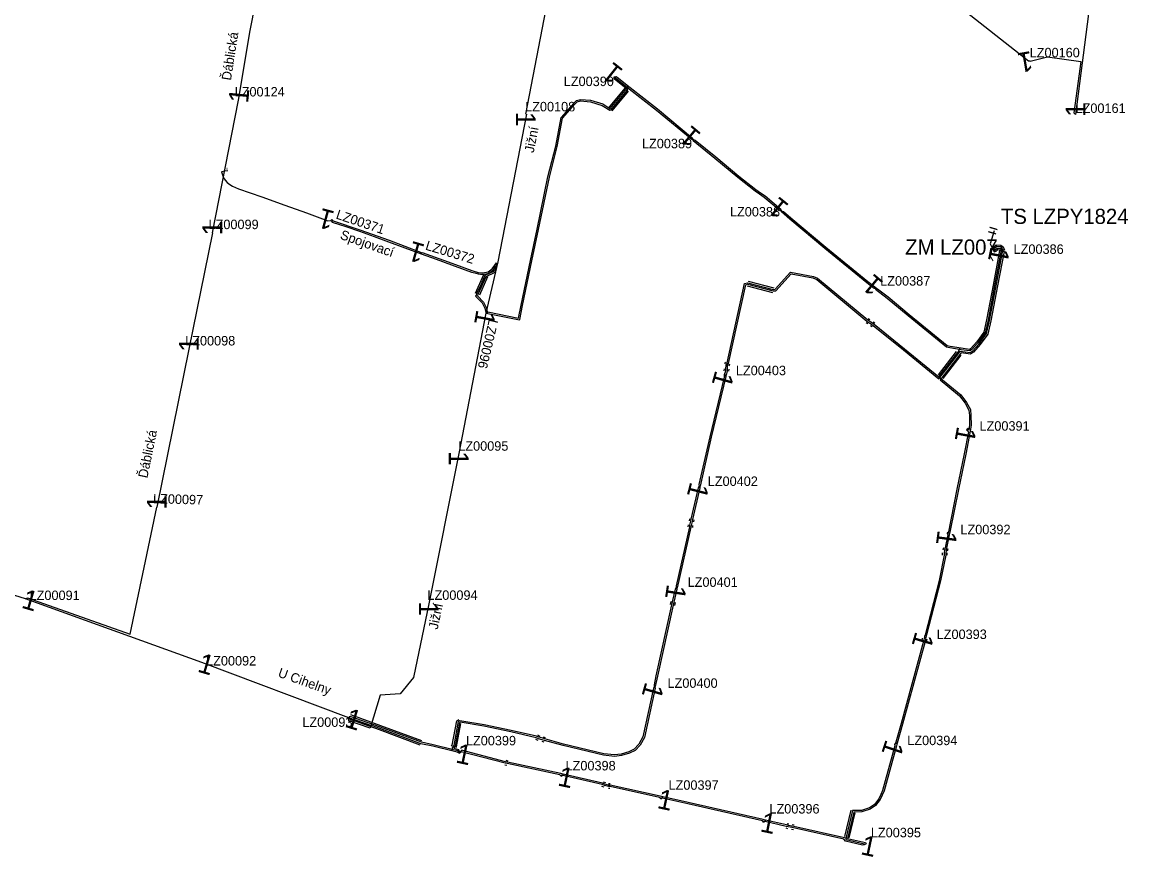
# Model space of a CAD drawing. Extents: x -736540 to -735418, y -1033000 to -1031598.
# Drawn here: x -735947.1 to -735655.8, y -1032999.9 to -1032780 of the extents above; entities that cross this region are included whole.
import ezdxf

# ---------------------------------------------------------------- set-up
doc = ezdxf.new("R2010")
doc.units = 0
for name, color, linetype in [('ftf_2010', 7, 'Continuous'), ('ftf_2060', 7, 'Continuous'), ('ftf_2100', 7, 'Continuous'), ('ftf_2140', 7, 'Continuous'), ('ftf_2210', 7, 'Continuous'), ('ftf_3010', 7, 'Continuous'), ('ftf_3010_ftf_3010_gtda_3015_gtda_3015_1', 7, 'Continuous'), ('ftf_3150', 7, 'Continuous'), ('ftf_3150_ftf_3150_gtda_3155_gtda_3155_1', 7, 'Continuous'), ('ftf_3160', 7, 'Continuous'), ('ftf_3160_ftf_3160_gtda_3165_gtda_3165_1', 7, 'Continuous'), ('ftf_3210', 7, 'Continuous'), ('ftf_nu', 7, 'Continuous')]:
    doc.layers.add(name, color=color, linetype=linetype)

msp = doc.modelspace()

# ---------------------------------------------------------------- linework, layer by layer
at = {"layer": 'ftf_2010'}
for points in [[(-735890.13, -1032800.57), (-735887.02, -1032782.2), (-735881.14, -1032752.3)], [(-735814.42, -1032804.25), (-735807.64, -1032769.14)], [(-735681.54, -1032790.25), (-735682.02, -1032790.23), (-735700.9, -1032775.41)], [(-735665.87, -1032775.1), (-735669.61, -1032804.33)], [(-735681.54, -1032790.25), (-735677.04, -1032789.09), (-735668.26, -1032790.39), (-735670.05, -1032803.87), (-735669.61, -1032804.33)], [(-735770.15, -1032811.01), (-735770.65, -1032810.99), (-735779.98, -1032803.26), (-735787.2, -1032797.62), (-735790.76, -1032794.7), (-735790.78, -1032794.47), (-735790.63, -1032794.3)], [(-735746.97, -1032829.81), (-735747.4, -1032829.7), (-735751.62, -1032826.16), (-735752.83, -1032825.33), (-735754.05, -1032824.5), (-735758.59, -1032820.92), (-735764.61, -1032815.88), (-735770.34, -1032811.25), (-735770.15, -1032811.01)], [(-735722.08, -1032850.15), (-735722.62, -1032850.2), (-735724.58, -1032848.7), (-735735.63, -1032839.65), (-735744.85, -1032831.9), (-735747.1, -1032829.96), (-735746.97, -1032829.81)], [(-735865.81, -1032832.27), (-735865.62, -1032832.46), (-735865.43, -1032832.64), (-735861.85, -1032833.84), (-735858.28, -1032835.04), (-735854.42, -1032836.45), (-735850.56, -1032837.85), (-735846.3, -1032839.42), (-735842.04, -1032840.99)], [(-735897.01, -1032835.52), (-735903.17, -1032866.17)], [(-735762.13, -1032872.86), (-735761.6, -1032872.99), (-735761.34, -1032871.9), (-735761.3, -1032871.42), (-735761.26, -1032870.37), (-735761.04, -1032869.89), (-735756.48, -1032849.16), (-735756.03, -1032849.04), (-735749.31, -1032850.8), (-735748.55, -1032850.74), (-735744.57, -1032846.33), (-735738.79, -1032847.35), (-735737.76, -1032847.81), (-735724.61, -1032858.75), (-735723.76, -1032859.29), (-735723.37, -1032859.57), (-735722.94, -1032859.87), (-735714.9, -1032866.34), (-735705.59, -1032873.97), (-735700.33, -1032867.22), (-735700, -1032866.68), (-735697.38, -1032867.04), (-735696.77, -1032866.66), (-735695.9, -1032865.68), (-735695.02, -1032864.7), (-735693.06, -1032861.98), (-735692.28, -1032858.62), (-735690.53, -1032849.43), (-735688.78, -1032840.08), (-735688.99, -1032839.39), (-735689.37, -1032839.14), (-735690.35, -1032839.1), (-735690.97, -1032839.59), (-735691.03, -1032840.5)], [(-735691.03, -1032840.5), (-735690.72, -1032839.9), (-735690.22, -1032839.5), (-735689.5, -1032839.53), (-735689.33, -1032839.65), (-735689.19, -1032840.1), (-735690.92, -1032849.35), (-735692.67, -1032858.54), (-735693.43, -1032861.81), (-735695.34, -1032864.45), (-735697.03, -1032866.35), (-735697.47, -1032866.62), (-735699.77, -1032866.31), (-735702.7, -1032865.83), (-735703.58, -1032865.59), (-735713.72, -1032857.4), (-735719.26, -1032852.77), (-735722.3, -1032850.44), (-735722.08, -1032850.15)], [(-735691.03, -1032840.5), (-735691.22, -1032839.28), (-735690.49, -1032838.69), (-735689.25, -1032838.74), (-735688.64, -1032839.14), (-735688.37, -1032840.06), (-735689.19, -1032840.1), (-735689.53, -1032840.07)], [(-735842.04, -1032840.99), (-735838.04, -1032842.44), (-735834.04, -1032843.89), (-735831.41, -1032844.85), (-735828.78, -1032845.82), (-735827.9, -1032846.07), (-735827.01, -1032846.31), (-735826.36, -1032846.36), (-735825.71, -1032846.41), (-735824.96, -1032846.28), (-735824.21, -1032846.14), (-735823.58, -1032845.7), (-735822.94, -1032845.26), (-735822.76, -1032844.77), (-735822.57, -1032844.28), (-735822.76, -1032844.97), (-735822.94, -1032845.66), (-735824.09, -1032846.21), (-735825.24, -1032846.76), (-735826.32, -1032849.18), (-735827.39, -1032851.6), (-735827.54, -1032851.91), (-735827.69, -1032852.21), (-735826.81, -1032853.09), (-735825.92, -1032853.98), (-735825.22, -1032855.33), (-735825.08, -1032855.99), (-735824.95, -1032856.66)], [(-735689.53, -1032840.07), (-735688.44, -1032840.45), (-735690.14, -1032849.5), (-735691.89, -1032858.71), (-735692.68, -1032862.15), (-735694.71, -1032864.95), (-735696.51, -1032866.97), (-735697.29, -1032867.45), (-735699.75, -1032867.12), (-735704.8, -1032873.66), (-735705.27, -1032874.24), (-735700.14, -1032878.45), (-735698.72, -1032880.38), (-735697.71, -1032882.2), (-735697.58, -1032883.66), (-735697.52, -1032886.18), (-735697.76, -1032887.52), (-735698.33, -1032887.41)], [(-735824.95, -1032856.66), (-735832.11, -1032893.62)], [(-735903.17, -1032866.17), (-735911.66, -1032907.76)], [(-735768.71, -1032902.2), (-735768.44, -1032902.26), (-735765.48, -1032889.3), (-735761.69, -1032873.38), (-735762.13, -1032872.86)], [(-735698.33, -1032887.41), (-735697.84, -1032887.91), (-735698.91, -1032893.74), (-735700.84, -1032903.07), (-735703.2, -1032914.71), (-735703.4, -1032914.67)], [(-735832.11, -1032893.62), (-735840.01, -1032933.23)], [(-735774.72, -1032928.94), (-735774.46, -1032929), (-735770.86, -1032913.07), (-735770.79, -1032912.58), (-735770.55, -1032911.53), (-735770.45, -1032911.03), (-735768.53, -1032902.65), (-735768.71, -1032902.2)], [(-735946.21, -1032931.9), (-735945.72, -1032931.67), (-735918.64, -1032941.23), (-735911.66, -1032907.76)], [(-735703.4, -1032914.67), (-735703.28, -1032915.1), (-735703.96, -1032918.49), (-735704.1, -1032919.12), (-735704.22, -1032919.85), (-735704.22, -1032920.38), (-735705.58, -1032927.06), (-735709.33, -1032941.73), (-735709.43, -1032941.7)], [(-735946.21, -1032931.9), (-735980.57, -1032921.21)], [(-735780.57, -1032954.97), (-735780.26, -1032955.04), (-735779.66, -1032952.3), (-735775.55, -1032933.63), (-735775.37, -1032932.82), (-735774.55, -1032929.39), (-735774.72, -1032928.94)], [(-735899.81, -1032948.74), (-735946.21, -1032931.9)], [(-735840.01, -1032933.23), (-735844, -1032952.69), (-735847.53, -1032956.96), (-735852.76, -1032957.32), (-735855.45, -1032966.04), (-735861.06, -1032964.03), (-735861.02, -1032963.29)], [(-735709.43, -1032941.7), (-735709.42, -1032942.11), (-735709.5, -1032942.41), (-735709.64, -1032943.11), (-735715.59, -1032964.82), (-735717.09, -1032970.28), (-735717.3, -1032970.22)], [(-735861.02, -1032963.29), (-735899.81, -1032948.74)], [(-735717.3, -1032970.22), (-735717.2, -1032970.66), (-735720.43, -1032982.42), (-735720.92, -1032983.5), (-735721.41, -1032984.59), (-735722.57, -1032986.1), (-735723.86, -1032986.98), (-735726.01, -1032987.67), (-735728.33, -1032987.72), (-735730.09, -1032995.06), (-735730.16, -1032995.37), (-735725.25, -1032996.5), (-735725.22, -1032996.55), (-735725.27, -1032996.78)], [(-735805.09, -1032978.66), (-735805.43, -1032978.32), (-735819.34, -1032975.35), (-735819.86, -1032975.25), (-735831.85, -1032972.11), (-735831.98, -1032972.6)], [(-735778.89, -1032984.61), (-735779.23, -1032984.3), (-735792.25, -1032981.4), (-735792.67, -1032981.39), (-735793.72, -1032981.1), (-735794.33, -1032980.89), (-735805.04, -1032978.4), (-735805.09, -1032978.66)], [(-735751.78, -1032990.77), (-735752.12, -1032990.45), (-735771.76, -1032985.96), (-735778.83, -1032984.39), (-735778.89, -1032984.61)], [(-735725.27, -1032996.78), (-735725.73, -1032996.8), (-735730.24, -1032995.76), (-735730.68, -1032995.25), (-735743.89, -1032992.29), (-735744.39, -1032992.22), (-735745.35, -1032992.02), (-735745.83, -1032991.88), (-735751.73, -1032990.54), (-735751.78, -1032990.77)]]:
    msp.add_lwpolyline(points, dxfattribs=at)
at = {"layer": 'ftf_2060'}
msp.add_lwpolyline([(-735691.03, -1032834.95), (-735692.12, -1032838.43), (-735691.03, -1032840.5)], dxfattribs=at)
at = {"layer": 'ftf_2100'}
for points in [[(-735824.91, -1032856.67), (-735816.11, -1032858.42), (-735816, -1032858.36), (-735815.27, -1032854.66), (-735812.82, -1032842.87), (-735811.06, -1032834.61), (-735808.21, -1032820.8), (-735806.17, -1032812.74), (-735804.74, -1032805.31), (-735801.54, -1032801.59), (-735800.87, -1032801), (-735800, -1032800.75), (-735797.43, -1032800.95), (-735794.32, -1032801.91), (-735792.33, -1032803.17), (-735791.95, -1032803.08), (-735787.66, -1032797.89), (-735787.56, -1032797.84), (-735791.14, -1032794.9), (-735791.19, -1032794.42), (-735790.63, -1032794.3)], [(-735897.01, -1032835.52), (-735890.13, -1032800.57)], [(-735814.22, -1032804.25), (-735821.8, -1032843.1), (-735824.95, -1032856.66)], [(-735892.91, -1032819.17), (-735893.74, -1032819.28), (-735894.57, -1032819.39), (-735894.32, -1032820.21), (-735894.07, -1032821.04), (-735893.59, -1032821.64), (-735893.12, -1032822.24), (-735892.41, -1032822.74), (-735891.7, -1032823.24), (-735890.92, -1032823.57), (-735890.13, -1032823.9), (-735884, -1032826.04), (-735877.87, -1032828.17), (-735872.21, -1032830.23), (-735866.56, -1032832.3), (-735865.81, -1032832.27)], [(-735780.57, -1032954.97), (-735780.34, -1032955.43), (-735783.19, -1032968.43), (-735784.34, -1032970.47), (-735785.65, -1032971.86), (-735787.12, -1032972.63), (-735789.24, -1032973.21), (-735791.09, -1032973.43), (-735793.94, -1032973.12), (-735804.57, -1032970.59), (-735809.54, -1032969.22), (-735810.08, -1032969.04), (-735811.09, -1032968.8), (-735811.71, -1032968.54), (-735818.36, -1032966.98), (-735825.46, -1032965.52), (-735831.72, -1032964.45), (-735831.89, -1032964.55), (-735833.04, -1032970.75), (-735833.35, -1032971.23), (-735833.38, -1032971.3), (-735832.13, -1032971.63), (-735831.98, -1032972.6)], [(-735831.98, -1032972.6), (-735832.24, -1032972.01), (-735833.5, -1032971.68), (-735838.87, -1032970.36), (-735841.94, -1032969.73), (-735852.74, -1032965.73), (-735860.66, -1032962.9), (-735860.93, -1032963.05), (-735861.02, -1032963.29)]]:
    msp.add_lwpolyline(points, dxfattribs=at)
at = {"layer": 'ftf_2140'}
for points in [[(-735770.15, -1032811.01), (-735770.5, -1032810.6), (-735779.73, -1032802.95), (-735786.95, -1032797.31), (-735790.32, -1032794.54), (-735790.63, -1032794.3), (-735790.32, -1032794.55)], [(-735824.56, -1032856.58), (-735824.44, -1032856.35), (-735816.33, -1032857.96), (-735815.66, -1032854.58), (-735813.21, -1032842.79), (-735811.45, -1032834.53), (-735808.6, -1032820.71), (-735806.56, -1032812.65), (-735805.12, -1032805.13), (-735801.82, -1032801.31), (-735801.07, -1032800.64), (-735800.04, -1032800.35), (-735797.35, -1032800.55), (-735794.15, -1032801.54), (-735792.26, -1032802.74), (-735792.17, -1032802.72), (-735787.39, -1032796.95)], [(-735746.97, -1032829.81), (-735747.22, -1032829.34), (-735751.38, -1032825.84), (-735752.61, -1032825), (-735753.81, -1032824.18), (-735758.34, -1032820.61), (-735764.35, -1032815.57), (-735769.78, -1032811.19), (-735770.15, -1032811.01)], [(-735722.08, -1032850.15), (-735722.5, -1032849.79), (-735724.33, -1032848.38), (-735735.38, -1032839.34), (-735744.59, -1032831.6), (-735746.53, -1032829.92), (-735746.97, -1032829.81)], [(-735865.81, -1032832.27), (-735865.53, -1032831.98), (-735865.22, -1032832.29), (-735858.15, -1032834.66), (-735850.42, -1032837.47), (-735842.21, -1032840.55), (-735842.04, -1032840.99)], [(-735842.04, -1032840.99), (-735841.77, -1032840.67), (-735841.77, -1032840.66), (-735833.9, -1032843.51), (-735828.66, -1032845.44), (-735826.94, -1032845.91), (-735825.73, -1032846.01), (-735824.37, -1032845.76), (-735823.27, -1032845), (-735822.16, -1032843.36), (-735822.6, -1032845.94), (-735824.93, -1032847.06), (-735827.03, -1032851.77), (-735827.2, -1032852.13), (-735825.59, -1032853.74), (-735824.84, -1032855.2), (-735824.56, -1032856.58), (-735824.95, -1032856.66)], [(-735691.03, -1032840.5), (-735690.49, -1032840.33), (-735690.4, -1032840.16), (-735690.09, -1032839.91), (-735689.66, -1032839.93), (-735689.6, -1032840.12), (-735691.32, -1032849.28), (-735693.06, -1032858.46), (-735693.8, -1032861.64), (-735695.65, -1032864.2), (-735697.29, -1032866.04), (-735697.56, -1032866.21), (-735699.71, -1032865.91), (-735702.62, -1032865.44), (-735703.4, -1032865.23), (-735713.47, -1032857.09), (-735719.01, -1032852.46), (-735721.74, -1032850.37), (-735722.08, -1032850.15), (-735721.76, -1032850.39)], [(-735689.6, -1032840.12), (-735689.53, -1032840.07)], [(-735762.04, -1032872.47), (-735762.13, -1032872.86), (-735761.74, -1032871.84), (-735761.7, -1032871.39), (-735761.65, -1032870.28), (-735761.42, -1032869.76), (-735756.82, -1032848.83), (-735756.03, -1032848.63), (-735749.27, -1032850.39), (-735748.74, -1032850.35), (-735744.72, -1032845.9), (-735738.68, -1032846.96), (-735737.55, -1032847.47), (-735724.37, -1032858.43), (-735723.53, -1032858.96), (-735723.13, -1032859.25), (-735722.7, -1032859.55), (-735714.65, -1032866.02), (-735705.66, -1032873.4), (-735700.66, -1032866.99), (-735699.97, -1032865.87)], [(-735768.71, -1032902.2), (-735768.74, -1032901.78), (-735765.87, -1032889.21), (-735762.13, -1032873.48), (-735762.13, -1032872.86)], [(-735705.66, -1032873.4), (-735699.85, -1032878.18), (-735698.38, -1032880.16), (-735697.32, -1032882.08), (-735697.18, -1032883.64), (-735697.12, -1032886.21), (-735697.3, -1032887.19)], [(-735697.3, -1032887.19), (-735697.4, -1032887.77), (-735698.52, -1032893.82), (-735700.45, -1032903.15), (-735702.73, -1032914.4)], [(-735697.3, -1032887.19), (-735697.86, -1032887.09), (-735698.33, -1032887.41)], [(-735774.72, -1032928.94), (-735774.76, -1032928.52), (-735771.26, -1032913), (-735771.19, -1032912.51), (-735770.94, -1032911.45), (-735770.85, -1032910.95), (-735768.94, -1032902.68), (-735768.71, -1032902.2)], [(-735702.73, -1032914.4), (-735702.86, -1032915.09), (-735703.57, -1032918.58), (-735703.71, -1032919.19), (-735703.82, -1032919.88), (-735703.82, -1032920.42), (-735705.2, -1032927.15), (-735708.84, -1032941.44)], [(-735702.73, -1032914.4), (-735703.12, -1032914.32), (-735703.4, -1032914.67)], [(-735780.57, -1032954.97), (-735780.56, -1032954.56), (-735780.05, -1032952.22), (-735775.94, -1032933.54), (-735775.76, -1032932.73), (-735774.97, -1032929.42), (-735774.72, -1032928.94)], [(-735708.84, -1032941.44), (-735709.02, -1032942.16), (-735709.11, -1032942.5), (-735709.25, -1032943.2), (-735715.21, -1032964.92), (-735716.6, -1032970)], [(-735709.43, -1032941.7), (-735708.94, -1032941.41), (-735708.84, -1032941.44)], [(-735780.57, -1032954.97), (-735780.76, -1032955.48), (-735783.57, -1032968.29), (-735784.67, -1032970.23), (-735785.9, -1032971.54), (-735787.27, -1032972.26), (-735789.32, -1032972.82), (-735791.09, -1032973.03), (-735793.88, -1032972.73), (-735804.47, -1032970.2), (-735809.43, -1032968.84), (-735809.97, -1032968.66), (-735810.97, -1032968.42), (-735811.59, -1032968.15), (-735818.28, -1032966.59), (-735825.39, -1032965.13), (-735831.79, -1032964.03), (-735832.25, -1032964.29), (-735833.42, -1032970.6), (-735833.72, -1032971.05), (-735834.02, -1032971.97)], [(-735831.98, -1032972.6), (-735832.52, -1032972.35), (-735833.6, -1032972.07), (-735838.96, -1032970.75), (-735842.05, -1032970.12), (-735852.88, -1032966.11), (-735854.84, -1032965.41), (-735855.23, -1032965.32), (-735861.02, -1032963.29)], [(-735716.6, -1032970), (-735716.79, -1032970.67), (-735720.05, -1032982.56), (-735720.56, -1032983.67), (-735721.07, -1032984.79), (-735722.29, -1032986.4), (-735723.69, -1032987.34), (-735725.94, -1032988.06), (-735728.01, -1032988.11), (-735729.68, -1032995.07), (-735724.98, -1032996.15), (-735724.8, -1032996.48), (-735725.27, -1032996.78)], [(-735717.3, -1032970.22), (-735716.81, -1032969.94), (-735716.6, -1032970)], [(-735831.98, -1032972.6), (-735831.49, -1032972.31), (-735831.36, -1032971.83)], [(-735804.56, -1032978.1), (-735805.23, -1032977.95), (-735819.26, -1032974.96), (-735819.77, -1032974.86), (-735831.36, -1032971.83)], [(-735805.09, -1032978.66), (-735804.62, -1032978.36), (-735804.56, -1032978.1)], [(-735778.36, -1032984.08), (-735779.03, -1032983.93), (-735792.2, -1032981), (-735792.61, -1032980.99), (-735793.6, -1032980.72), (-735794.22, -1032980.5), (-735804.56, -1032978.1)], [(-735778.89, -1032984.61), (-735778.41, -1032984.31), (-735778.36, -1032984.08)], [(-735751.25, -1032990.24), (-735751.92, -1032990.08), (-735771.67, -1032985.57), (-735778.36, -1032984.08)], [(-735751.78, -1032990.77), (-735751.3, -1032990.46), (-735751.25, -1032990.24)], [(-735729.68, -1032995.06), (-735743.82, -1032991.9), (-735744.32, -1032991.82), (-735745.26, -1032991.63), (-735745.73, -1032991.5), (-735751.25, -1032990.24)]]:
    msp.add_lwpolyline(points, dxfattribs=at)
at = {"layer": 'ftf_3210'}
for p, q in [((-735825.61, -1032846.6), (-735827.76, -1032851.44)), ((-735824.51, -1032847.08), (-735826.66, -1032851.92)), ((-735724.8, -1032859.1), (-735724.34, -1032859.36)), ((-735724.23, -1032858.05), (-735723.76, -1032858.31)), ((-735723.6, -1032859.9), (-735723.17, -1032860.2)), ((-735722.91, -1032858.92), (-735722.48, -1032859.22)), ((-735762.14, -1032871.83), (-735762.1, -1032871.35)), ((-735761.99, -1032870.05), (-735761.77, -1032869.56)), ((-735760.94, -1032871.93), (-735760.9, -1032871.45)), ((-735760.89, -1032870.53), (-735760.68, -1032870.05)), ((-735771.34, -1032911.38), (-735771.24, -1032910.88)), ((-735770.16, -1032911.61), (-735770.06, -1032911.1)), ((-735771.65, -1032912.97), (-735771.59, -1032912.47)), ((-735770.47, -1032913.13), (-735770.4, -1032912.63)), ((-735704.62, -1032920.38), (-735704.62, -1032919.85)), ((-735704.49, -1032919.03), (-735704.35, -1032918.41)), ((-735703.42, -1032920.39), (-735703.42, -1032919.85)), ((-735703.32, -1032919.29), (-735703.18, -1032918.67)), ((-735776.33, -1032933.46), (-735776.15, -1032932.65)), ((-735775.15, -1032933.71), (-735774.98, -1032932.91)), ((-735710.03, -1032943.03), (-735709.89, -1032942.33)), ((-735708.86, -1032943.27), (-735708.72, -1032942.57)), ((-735811.87, -1032968.9), (-735811.25, -1032969.17)), ((-735811.39, -1032967.8), (-735810.78, -1032968.07)), ((-735810.21, -1032969.42), (-735809.67, -1032969.6)), ((-735809.83, -1032968.28), (-735809.29, -1032968.47)), ((-735819.94, -1032975.65), (-735819.42, -1032975.75)), ((-735819.71, -1032974.47), (-735819.19, -1032974.57)), ((-735794.46, -1032981.27), (-735793.85, -1032981.48)), ((-735794.07, -1032980.13), (-735793.46, -1032980.35)), ((-735792.68, -1032981.79), (-735792.26, -1032981.8)), ((-735792.65, -1032980.59), (-735792.23, -1032980.6)), ((-735745.94, -1032992.27), (-735745.46, -1032992.4)), ((-735745.61, -1032991.11), (-735745.14, -1032991.25)), ((-735744.45, -1032992.61), (-735743.95, -1032992.69)), ((-735744.27, -1032991.43), (-735743.77, -1032991.5))]:
    msp.add_line(p, q, dxfattribs=at)
for points in [[(-735792.56, -1032802.57), (-735788.27, -1032797.38)], [(-735791.64, -1032803.34), (-735787.35, -1032798.15)], [(-735825.24, -1032846.76), (-735825.78, -1032847.97), (-735826.32, -1032849.18), (-735826.85, -1032850.39), (-735827.39, -1032851.6)], [(-735755.82, -1032848.27), (-735749.11, -1032850.02)], [(-735756.13, -1032849.43), (-735749.41, -1032851.18)], [(-735705.75, -1032872.92), (-735700.97, -1032866.73)], [(-735704.48, -1032873.9), (-735699.7, -1032867.71)], [(-735842.22, -1032970.48), (-735853.01, -1032966.48), (-735860.92, -1032963.66)], [(-735841.81, -1032969.35), (-735852.6, -1032965.36), (-735860.52, -1032962.53)], [(-735834.02, -1032970.79), (-735833.8, -1032970.45), (-735832.61, -1032964.03), (-735832.1, -1032963.75)], [(-735832.8, -1032971.11), (-735832.67, -1032970.9), (-735831.54, -1032964.81), (-735831.52, -1032964.8)], [(-735730.38, -1032994.58), (-735728.72, -1032987.63)], [(-735729.21, -1032994.86), (-735727.65, -1032988.3)]]:
    msp.add_lwpolyline(points, dxfattribs=at)

# ---------------------------------------------------------------- texts
at = {"layer": 'ftf_2210'}
msp.add_text('-', height=2, rotation=270, dxfattribs=at).set_placement((-735893.91, -1032818.17))
at = {"layer": 'ftf_3010'}
for rotation, p in [(189.6932, (-735681.34, -1032787.57)), (141.4364, (-735788.51, -1032792.67)), (84.3343, (-735887.61, -1032801.47)), (90, (-735667.01, -1032804.97)), (270, (-735817.02, -1032803.6)), (139.926, (-735767.98, -1032809.44)), (141.0044, (-735744.83, -1032828.2)), (164.8921, (-735864.51, -1032829.93)), (90, (-735894.41, -1032836.17)), (164.0617, (-735840.7, -1032838.67)), (258.5148, (-735691.95, -1032838.92)), (139.9835, (-735719.91, -1032848.57)), (259.8011, (-735827.39, -1032855.56)), (90, (-735900.57, -1032866.82)), (254.3302, (-735764.46, -1032871.54)), (259.4656, (-735700.77, -1032886.3)), (270, (-735834.71, -1032892.97)), (255.5744, (-735771.07, -1032900.92)), (90, (-735909.06, -1032908.41)), (262.3825, (-735705.89, -1032913.68)), (343.7108, (-735947.56, -1032934.21)), (261.4521, (-735777.2, -1032927.91)), (270, (-735842.61, -1032932.59)), (253.8532, (-735711.75, -1032940.35)), (343.5687, (-735901.17, -1032951.05)), (253.8937, (-735782.89, -1032953.63)), (343.017, (-735862.39, -1032965.59)), (348, (-735833.15, -1032975.01)), (251.552, (-735719.56, -1032968.78)), (348, (-735806.27, -1032981.07)), (348, (-735780.06, -1032987.02)), (348.5612, (-735752.93, -1032993.18)), (348, (-735726.45, -1032999.19))]:
    msp.add_text('1', height=5.2, rotation=rotation, dxfattribs=at).set_placement(p)
at = {"layer": 'ftf_3010_ftf_3010_gtda_3015_gtda_3015_1'}
for s, p in [('LZ00160', (-735681.69, -1032789.25)), ('LZ00390', (-735804.43, -1032796.83)), ('LZ00161', (-735669.61, -1032803.9)), ('LZ00389', (-735783.83, -1032813.22)), ('LZ00388', (-735760.65, -1032831.18)), ('LZ00386', (-735685.93, -1032841.04)), ('LZ00387', (-735721.08, -1032849.4)), ('LZ00403', (-735759.09, -1032873.01)), ('LZ00391', (-735694.91, -1032887.63)), ('LZ00402', (-735766.5, -1032902.19)), ('LZ00392', (-735699.94, -1032914.91)), ('LZ00401', (-735771.8, -1032928.78)), ('LZ00091', (-735945.15, -1032932.25)), ('LZ00393', (-735706.19, -1032942.52)), ('LZ00092', (-735898.66, -1032949.5)), ('LZ00400', (-735777.1, -1032955.38)), ('LZ00093', (-735873.3, -1032965.67)), ('LZ00399', (-735830.2, -1032970.54)), ('LZ00394', (-735713.94, -1032970.48)), ('LZ00398', (-735803.96, -1032977.14)), ('LZ00397', (-735776.83, -1032982.24)), ('LZ00396', (-735750.25, -1032988.5)), ('LZ00395', (-735723.53, -1032994.76))]:
    msp.add_text(s, height=2.5, dxfattribs=at).set_placement(p)
for s, rotation, p in [('LZ00124', 0, (-735891.13, -1032799.57)), ('LZ00108', 0, (-735814.61, -1032803.49)), ('LZ00371', 341.3869, (-735864.63, -1032831.69)), ('LZ00099', 0, (-735898.01, -1032834.52)), ('LZ00372', 343.2201, (-735841.05, -1032839.89)), ('LZ00096', 256.7296, (-735824.1, -1032858.06)), ('LZ00098', 0, (-735904.17, -1032865.17)), ('LZ00095', 0, (-735832.22, -1032892.91)), ('LZ00097', 358.5076, (-735912.66, -1032906.76)), ('LZ00094', 0, (-735840.34, -1032932.2))]:
    msp.add_text(s, height=2.5, rotation=rotation, dxfattribs=at).set_placement(p)
at = {"layer": 'ftf_3150'}
msp.add_text('>', height=2.7, rotation=144.7924, dxfattribs=at).set_placement((-735689.93, -1032841.28))
at = {"layer": 'ftf_3150_ftf_3150_gtda_3155_gtda_3155_1'}
msp.add_text('ZM LZ007', height=4, dxfattribs=at).set_placement((-735714.49, -1032841.24))
at = {"layer": 'ftf_3160'}
msp.add_text('=', height=3.3, rotation=343.5755, dxfattribs=at).set_placement((-735693.08, -1032836.06))
at = {"layer": 'ftf_3160_ftf_3160_gtda_3165_gtda_3165_1'}
msp.add_text('TS LZPY1824', height=4, dxfattribs=at).set_placement((-735689.26, -1032833.15))
at = {"layer": 'ftf_nu'}
for s, rotation, p in [('Ďáblická', 81.1354, (-735892.12, -1032795.46)), ('Jižní', 79.0362, (-735812.35, -1032814.52)), ('Spojovací', 340.4488, (-735863.53, -1032837.02)), ('Ďáblická', 78.3791, (-735914.14, -1032900.27)), ('Jižní', 78.3947, (-735837.64, -1032940.11)), ('U Cihelny', 340.2936, (-735879.91, -1032952.39))]:
    msp.add_text(s, height=2.5, rotation=rotation, dxfattribs=at).set_placement(p)

doc.saveas('drawing.dxf')
